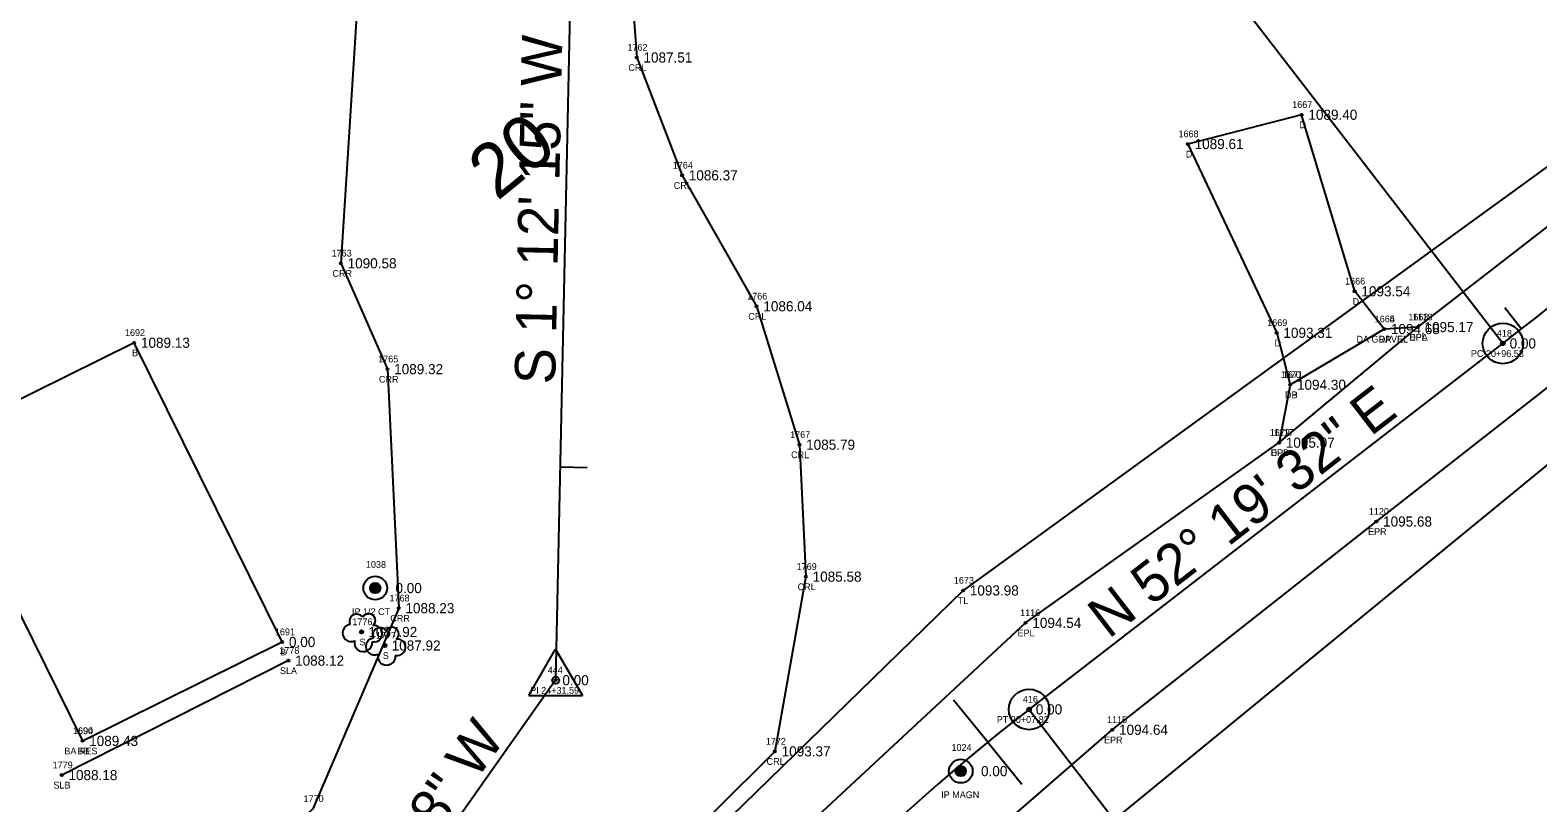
# Model space of a CAD drawing. Extents: x 1539151 to 1541799, y 1198646 to 1201165.
# Drawn here: x 1540139.3 to 1540362.7, y 1199640 to 1199754.4 of the extents above; entities that cross this region are included whole.
import ezdxf

# ---------------------------------------------------------------- set-up
doc = ezdxf.new("R2010")
doc.units = 0
for name, color, linetype in [('RD_EX_Bldg', 7, 'Continuous'), ('RD_EX_Bldg_txCode', 7, 'Continuous'), ('RD_EX_Driveway', 7, 'Continuous'), ('RD_EX_Driveway_txCode', 7, 'Continuous'), ('RD_EX_DV_Prop_txCode', 7, 'Continuous'), ('RD_EX_DV_PropPin', 7, 'Continuous'), ('RD_EX_H2O', 7, 'Continuous'), ('RD_EX_H2O_txCode', 7, 'Continuous'), ('RD_EX_Road', 7, 'Continuous'), ('RD_EX_Road_txCode', 7, 'Continuous'), ('RD_EX_TX_Bldg_ELEV', 7, 'Continuous'), ('RD_EX_TX_Driveway_ELEV', 7, 'Continuous'), ('RD_EX_TX_DV_Prop_ELEV', 7, 'Continuous'), ('RD_EX_TX_H2O_ELEV', 7, 'Continuous'), ('RD_EX_TX_Road_ELEV', 7, 'Continuous'), ('RD_EX_TX_VEG_ELEV', 7, 'Continuous'), ('RD_EX_VEG', 7, 'Continuous'), ('RD_EX_VEG_txCode', 7, 'Continuous'), ('RD_HC_Cl', 7, 'Continuous'), ('RD_HC_Data', 7, 'Continuous'), ('RD_HC_Data_Tic', 7, 'Continuous'), ('RD_HC_Survey_ELEV', 7, 'Continuous'), ('RD_HC_TX_Sta50', 7, 'Continuous'), ('RD_HC_txCode', 7, 'Continuous'), ('RD_SMD_Locator', 7, 'Continuous')]:
    doc.layers.add(name, color=color, linetype=linetype)

msp = doc.modelspace()

# ---------------------------------------------------------------- linework, layer by layer
at = {"layer": 'RD_EX_Bldg'}
msp.add_lwpolyline([(1540147.03, 1199649.13), (1540176.64, 1199663.78), (1540154.7, 1199708.11), (1540125.09, 1199693.46), (1540147.03, 1199649.13)], dxfattribs=at)
at = {"layer": 'RD_EX_Driveway'}
for points in [[(1540339.94, 1199710.14), (1540335.57, 1199715.73), (1540327.71, 1199741.89), (1540310.85, 1199737.55), (1540324.01, 1199709.58), (1540326.02, 1199701.89)], [(1540344.92, 1199710.43), (1540339.94, 1199710.14), (1540326.02, 1199701.89), (1540324.36, 1199693.31)]]:
    msp.add_lwpolyline(points, dxfattribs=at)
at = {"layer": 'RD_EX_DV_PropPin'}
for p, q in [((1540189.86, 1199671.26), (1540189.86, 1199672.29)), ((1540189.9, 1199671.22), (1540189.9, 1199672.32)), ((1540189.93, 1199671.19), (1540189.93, 1199672.35)), ((1540189.97, 1199671.16), (1540189.97, 1199672.38)), ((1540190, 1199671.14), (1540190, 1199672.41)), ((1540190.04, 1199671.12), (1540190.04, 1199672.43)), ((1540190.07, 1199671.1), (1540190.07, 1199672.45)), ((1540190.11, 1199671.08), (1540190.11, 1199672.46)), ((1540190.14, 1199671.06), (1540190.14, 1199672.48)), ((1540190.18, 1199671.05), (1540190.18, 1199672.49)), ((1540190.21, 1199671.04), (1540190.21, 1199672.5)), ((1540190.25, 1199671.03), (1540190.25, 1199672.51)), ((1540190.28, 1199671.02), (1540190.28, 1199672.52)), ((1540190.32, 1199671.02), (1540190.32, 1199672.53)), ((1540190.35, 1199671.01), (1540190.35, 1199672.53)), ((1540190.39, 1199671.01), (1540190.39, 1199672.53)), ((1540190.42, 1199671.01), (1540190.42, 1199672.53)), ((1540190.46, 1199671.01), (1540190.46, 1199672.53)), ((1540190.49, 1199671.01), (1540190.49, 1199672.53)), ((1540190.53, 1199671.02), (1540190.53, 1199672.53)), ((1540190.56, 1199671.02), (1540190.56, 1199672.52)), ((1540190.6, 1199671.03), (1540190.6, 1199672.51)), ((1540190.63, 1199671.04), (1540190.63, 1199672.5)), ((1540190.67, 1199671.05), (1540190.67, 1199672.49)), ((1540190.7, 1199671.06), (1540190.7, 1199672.48)), ((1540190.74, 1199671.08), (1540190.74, 1199672.46)), ((1540190.77, 1199671.1), (1540190.77, 1199672.45)), ((1540190.81, 1199671.12), (1540190.81, 1199672.43)), ((1540190.84, 1199671.14), (1540190.84, 1199672.41)), ((1540190.88, 1199671.16), (1540190.88, 1199672.38)), ((1540190.91, 1199671.19), (1540190.91, 1199672.35)), ((1540190.95, 1199671.22), (1540190.95, 1199672.32)), ((1540190.98, 1199671.26), (1540190.98, 1199672.29)), ((1540189.69, 1199671.58), (1540189.69, 1199671.97)), ((1540189.72, 1199671.47), (1540189.72, 1199672.07)), ((1540189.76, 1199671.4), (1540189.76, 1199672.14)), ((1540189.79, 1199671.35), (1540189.79, 1199672.2)), ((1540189.83, 1199671.3), (1540189.83, 1199672.25)), ((1540191.02, 1199671.3), (1540191.02, 1199672.25)), ((1540191.05, 1199671.35), (1540191.05, 1199672.2)), ((1540191.09, 1199671.4), (1540191.09, 1199672.14)), ((1540191.12, 1199671.47), (1540191.12, 1199672.07)), ((1540191.16, 1199671.58), (1540191.16, 1199671.97)), ((1540276.47, 1199644.45), (1540276.47, 1199644.84)), ((1540276.5, 1199644.35), (1540276.5, 1199644.94)), ((1540276.54, 1199644.28), (1540276.54, 1199645.02)), ((1540276.57, 1199644.22), (1540276.57, 1199645.07)), ((1540276.61, 1199644.17), (1540276.61, 1199645.12)), ((1540276.64, 1199644.13), (1540276.64, 1199645.16)), ((1540276.68, 1199644.1), (1540276.68, 1199645.2)), ((1540276.71, 1199644.06), (1540276.71, 1199645.23)), ((1540276.75, 1199644.04), (1540276.75, 1199645.26)), ((1540276.78, 1199644.01), (1540276.78, 1199645.28)), ((1540276.82, 1199643.99), (1540276.82, 1199645.3)), ((1540276.85, 1199643.97), (1540276.85, 1199645.32)), ((1540276.89, 1199643.95), (1540276.89, 1199645.34)), ((1540276.92, 1199643.94), (1540276.92, 1199645.35)), ((1540276.96, 1199643.93), (1540276.96, 1199645.37)), ((1540276.99, 1199643.92), (1540276.99, 1199645.38)), ((1540277.03, 1199643.91), (1540277.03, 1199645.39)), ((1540277.06, 1199643.9), (1540277.06, 1199645.39)), ((1540277.1, 1199643.89), (1540277.1, 1199645.4)), ((1540277.13, 1199643.89), (1540277.13, 1199645.4)), ((1540277.17, 1199643.89), (1540277.17, 1199645.41)), ((1540277.2, 1199643.89), (1540277.2, 1199645.41)), ((1540277.24, 1199643.89), (1540277.24, 1199645.41)), ((1540277.27, 1199643.89), (1540277.27, 1199645.4)), ((1540277.31, 1199643.89), (1540277.31, 1199645.4)), ((1540277.34, 1199643.9), (1540277.34, 1199645.39)), ((1540277.38, 1199643.91), (1540277.38, 1199645.39)), ((1540277.41, 1199643.92), (1540277.41, 1199645.38)), ((1540277.45, 1199643.93), (1540277.45, 1199645.37)), ((1540277.48, 1199643.94), (1540277.48, 1199645.35)), ((1540277.52, 1199643.95), (1540277.52, 1199645.34)), ((1540277.55, 1199643.97), (1540277.55, 1199645.32)), ((1540277.59, 1199643.99), (1540277.59, 1199645.3)), ((1540277.62, 1199644.01), (1540277.62, 1199645.28)), ((1540277.66, 1199644.04), (1540277.66, 1199645.26)), ((1540277.69, 1199644.06), (1540277.69, 1199645.23)), ((1540277.73, 1199644.1), (1540277.73, 1199645.2)), ((1540277.76, 1199644.13), (1540277.76, 1199645.16)), ((1540277.8, 1199644.17), (1540277.8, 1199645.12)), ((1540277.83, 1199644.22), (1540277.83, 1199645.07)), ((1540277.87, 1199644.28), (1540277.87, 1199645.02)), ((1540277.9, 1199644.35), (1540277.9, 1199644.94)), ((1540277.94, 1199644.45), (1540277.94, 1199644.84))]:
    msp.add_line(p, q, dxfattribs=at)
for centre, radius in [((1540190.42, 1199671.77), 1.75), ((1540190.42, 1199671.77), 0.761), ((1540277.2, 1199644.65), 1.75), ((1540277.2, 1199644.65), 0.761)]:
    msp.add_circle(centre, radius, dxfattribs=at)
at = {"layer": 'RD_EX_H2O'}
for points in [[(1540731.42, 1200240.96), (1540712.61, 1200188.05), (1540690.39, 1200137.17), (1540654.89, 1200108.18), (1540604.41, 1200084.34), (1540543.54, 1200035.6), (1540493.52, 1200006.6), (1540450.33, 1199977.65), (1540405.98, 1199942.24), (1540381.65, 1199909.97), (1540318.96, 1199864.02), (1540266.74, 1199845.63), (1540245.15, 1199841.34), (1540225.71, 1199832.2), (1540201, 1199803.23), (1540187.74, 1199758.03), (1540185.33, 1199719.88), (1540192.23, 1199704.2), (1540193.9, 1199668.79), (1540181.18, 1199639.07), (1540158, 1199617.15)], [(1540745.24, 1200145.69), (1540714.12, 1200111.24), (1540686.99, 1200083.09), (1540635.75, 1200037.11), (1540573.3, 1199996.4), (1540513.92, 1199967.81), (1540469.14, 1199939.84), (1540434.54, 1199909.73), (1540407.32, 1199874.45), (1540364.13, 1199846.32), (1540277.43, 1199809.38), (1540253.91, 1199804.21), (1540226.93, 1199780.46), (1540229.17, 1199750.37), (1540235.89, 1199732.91), (1540246.94, 1199713.51), (1540253.28, 1199693.01), (1540254.24, 1199673.46), (1540249.65, 1199647.58), (1540231.41, 1199629.45), (1540215.51, 1199604.28), (1540200.09, 1199580.59)]]:
    msp.add_lwpolyline(points, dxfattribs=at)
at = {"layer": 'RD_EX_Road'}
for points in [[(1540156.86, 1199508.27), (1540186.51, 1199551.73), (1540214.32, 1199591.31), (1540249.72, 1199632.22), (1540286.8, 1199666.61), (1540324.36, 1199693.31), (1540344.92, 1199710.43), (1540367.33, 1199727.77), (1540402.7, 1199760.37), (1540437.37, 1199795.58), (1540455.74, 1199815.52), (1540466.15, 1199827.23), (1540503.86, 1199868.5), (1540538.69, 1199906.78), (1540571.44, 1199944.18), (1540603.42, 1199982.61), (1540638.15, 1200019.15), (1540672.1, 1200056.68), (1540705.32, 1200094.04), (1540739.01, 1200131.56)], [(1540170.57, 1199494.63), (1540181.23, 1199508.28), (1540202.24, 1199541.54), (1540230.14, 1199581.95), (1540262.76, 1199618.79), (1540299.65, 1199650.78), (1540338.78, 1199681.63), (1540378.45, 1199712.68), (1540416.67, 1199747.15), (1540451.68, 1199783.64), (1540485.11, 1199820.19), (1540518.57, 1199856.95), (1540552.63, 1199894.89), (1540585.47, 1199932.32), (1540619.12, 1199969.78), (1540652.74, 1200007.33), (1540685.87, 1200044.5), (1540718.68, 1200081.33), (1540762.24, 1200130.19)]]:
    msp.add_lwpolyline(points, dxfattribs=at)
at = {"layer": 'RD_EX_VEG'}
msp.add_line((1540177.55, 1199661.02), (1540143.96, 1199644.07), dxfattribs=at)
for points in [[(1540712.01, 1200109.09), (1540564.8, 1199952.12), (1540511.25, 1199924.62), (1540488.55, 1199863.43), (1540394.02, 1199755.91), (1540277.54, 1199671.42), (1540233.54, 1199628.53), (1540200.18, 1199585.62), (1540155.93, 1199516.08), (1540069.9, 1199571.55)], [(1540836.37, 1200082.45), (1540794.45, 1200101.71), (1540758.65, 1200106.39), (1540697.29, 1200033.83), (1540560.39, 1199886.45), (1540422.51, 1199739.87), (1540382.08, 1199704.72), (1540267.52, 1199610.92), (1540233.68, 1199579.65), (1540209.33, 1199537.96), (1540187.75, 1199496.51), (1540221.64, 1199381.22)]]:
    msp.add_lwpolyline(points, dxfattribs=at)
for centre in [(1540188.4, 1199665.27), (1540191.86, 1199663.26)]:
    msp.add_circle(centre, 0.25, dxfattribs=at)
for centre, radius, start, end in [((1540187.68, 1199666.82), 1.08, 34.9763, 204.756), ((1540189.45, 1199666.98), 0.995, 308.7626, 152.0467), ((1540186.84, 1199665.12), 1.26, 96.4518, 294.734), ((1540190.24, 1199665), 1.22, 256.5667, 98.1046), ((1540191.14, 1199664.81), 1.08, 34.9763, 204.756), ((1540192.91, 1199664.97), 0.995, 308.7626, 152.0467), ((1540188.65, 1199663.68), 1.32, 166.8827, 5.7589), ((1540190.3, 1199663.11), 1.26, 96.4518, 294.734), ((1540193.7, 1199662.98), 1.22, 256.5667, 98.1046), ((1540192.11, 1199661.67), 1.32, 166.8827, 5.7589)]:
    msp.add_arc(centre, radius, start, end, dxfattribs=at)
at = {"layer": 'RD_HC_Cl'}
for p, q in [((1540219.98, 1199792.28), (1540217.16, 1199658.12)), ((1540287.32, 1199653.79), (1540357.53, 1199708.01)), ((1540217.16, 1199658.12), (1540172.44, 1199594.87))]:
    msp.add_line(p, q, dxfattribs=at)
for centre, radius, start, end in [((1539929.71, 1200262.06), 700, 307.67455, 318.32753), ((1540470.67, 1199416.35), 300, 127.6745, 145.5923)]:
    msp.add_arc(centre, radius, start, end, dxfattribs=at)
at = {"layer": 'RD_HC_Data'}
for p, q in [((1540357.53, 1199708.01), (1540286.37, 1199800.18)), ((1540213.19, 1199655.83), (1540217.16, 1199662.71)), ((1540217.16, 1199662.71), (1540221.13, 1199655.83)), ((1540213.19, 1199655.83), (1540221.13, 1199655.83)), ((1540287.32, 1199653.79), (1540357.97, 1199562.31))]:
    msp.add_line(p, q, dxfattribs=at)
for centre, radius in [((1540357.53, 1199708.01), 3), ((1540357.53, 1199708.01), 0.282), ((1540217.16, 1199658.12), 0.529), ((1540287.32, 1199653.79), 3), ((1540287.32, 1199653.79), 0.282)]:
    msp.add_circle(centre, radius, dxfattribs=at)
at = {"layer": 'RD_HC_Data_Tic'}
for p, q in [((1540360.28, 1199710.14), (1540357.82, 1199713.29)), ((1540217.83, 1199689.71), (1540221.83, 1199689.62)), ((1540281.2, 1199648.94), (1540276.14, 1199655.14)), ((1540281.2, 1199648.94), (1540286.25, 1199642.73))]:
    msp.add_line(p, q, dxfattribs=at)
at = {"layer": 'RD_SMD_Locator'}
for centre in [(1540229.17, 1199750.37), (1540327.71, 1199741.89), (1540310.85, 1199737.55), (1540235.89, 1199732.91), (1540185.33, 1199719.88), (1540335.57, 1199715.73), (1540246.94, 1199713.51), (1540339.94, 1199710.14), (1540339.94, 1199710.14), (1540344.92, 1199710.43), (1540344.92, 1199710.43), (1540154.7, 1199708.11), (1540324.01, 1199709.58), (1540357.53, 1199708.01), (1540192.23, 1199704.2), (1540326.02, 1199701.89), (1540326.02, 1199701.89), (1540253.28, 1199693.01), (1540324.36, 1199693.31), (1540324.36, 1199693.31), (1540338.78, 1199681.63), (1540254.24, 1199673.46), (1540190.42, 1199671.77), (1540277.54, 1199671.42), (1540193.9, 1199668.79), (1540286.8, 1199666.61), (1540176.64, 1199663.78), (1540188.4, 1199665.27), (1540191.86, 1199663.26), (1540177.55, 1199661.02), (1540217.16, 1199658.12), (1540287.32, 1199653.79), (1540299.65, 1199650.78), (1540147.03, 1199649.13), (1540147.03, 1199649.13), (1540249.65, 1199647.58), (1540143.96, 1199644.07), (1540277.2, 1199644.65)]:
    msp.add_circle(centre, 0.15, dxfattribs=at)

# ---------------------------------------------------------------- texts
at = {"layer": 'RD_EX_Bldg_txCode'}
for s, p in [('1692', (1540153.33, 1199709.11)), ('B', (1540154.39, 1199706.11)), ('1691', (1540175.55, 1199664.78)), ('B', (1540176.33, 1199661.78)), ('1690', (1540145.62, 1199650.13)), ('1694', (1540145.66, 1199650.13)), ('BA RES', (1540144.35, 1199647.13)), ('BB', (1540146.25, 1199647.13))]:
    msp.add_text(s, height=1, dxfattribs=at).set_placement(p)
at = {"layer": 'RD_EX_Driveway_txCode'}
for s, p in [('1667', (1540326.31, 1199742.89)), ('1668', (1540309.46, 1199738.55)), ('D', (1540327.4, 1199739.89)), ('D', (1540310.54, 1199735.55)), ('1666', (1540334.15, 1199716.73)), ('D', (1540335.26, 1199713.73)), ('1669', (1540322.61, 1199710.58)), ('1664', (1540338.54, 1199711.14)), ('1665', (1540338.54, 1199711.14)), ('1663', (1540343.52, 1199711.43)), ('D', (1540323.7, 1199707.58)), ('DA GRAVEL', (1540335.83, 1199708.14)), ('DP', (1540339.16, 1199708.14)), ('DPA', (1540343.65, 1199708.43)), ('1670', (1540324.61, 1199702.89)), ('1671', (1540324.93, 1199702.89)), ('DB', (1540325.24, 1199699.89)), ('DP', (1540325.24, 1199699.89)), ('1672', (1540322.99, 1199694.31)), ('DPB', (1540323.11, 1199691.31))]:
    msp.add_text(s, height=1, dxfattribs=at).set_placement(p)
at = {"layer": 'RD_EX_DV_Prop_txCode'}
for s, p in [('1038', (1540189.04, 1199674.77)), ('IP 1/2 CT', (1540186.97, 1199667.77)), ('1024', (1540275.82, 1199647.65)), ('IP MAGN', (1540274.29, 1199640.65))]:
    msp.add_text(s, height=1, dxfattribs=at).set_placement(p)
at = {"layer": 'RD_EX_H2O_txCode'}
for s, p in [('1762', (1540227.8, 1199751.37)), ('CRL', (1540227.94, 1199748.37)), ('1764', (1540234.52, 1199733.91)), ('CRL', (1540234.66, 1199730.91)), ('1763', (1540183.96, 1199720.88)), ('CRR', (1540184.08, 1199717.88)), ('1766', (1540245.54, 1199714.51)), ('CRL', (1540245.71, 1199711.51)), ('1765', (1540190.86, 1199705.2)), ('CRR', (1540190.97, 1199702.2)), ('1767', (1540251.91, 1199694.01)), ('CRL', (1540252.05, 1199691.01)), ('1769', (1540252.87, 1199674.46)), ('CRL', (1540253.02, 1199671.46)), ('1768', (1540192.53, 1199669.79)), ('CRR', (1540192.65, 1199666.79)), ('1772', (1540248.31, 1199648.58)), ('CRL', (1540248.42, 1199645.58)), ('1770', (1540179.8, 1199640.07))]:
    msp.add_text(s, height=1, dxfattribs=at).set_placement(p)
at = {"layer": 'RD_EX_Road_txCode'}
for s, p in [('1118', (1540344.14, 1199711.43)), ('EPL', (1540343.71, 1199708.43)), ('1117', (1540323.58, 1199694.31)), ('EPL', (1540323.16, 1199691.31)), ('1120', (1540337.67, 1199682.63)), ('EPR', (1540337.55, 1199679.63)), ('1116', (1540286, 1199667.61)), ('EPL', (1540285.6, 1199664.61)), ('1115', (1540298.87, 1199651.78)), ('EPR', (1540298.42, 1199648.78))]:
    msp.add_text(s, height=1, dxfattribs=at).set_placement(p)
at = {"layer": 'RD_EX_TX_Bldg_ELEV'}
for s, p in [('1089.13', (1540155.7, 1199707.36)), ('0.00', (1540177.64, 1199663.03)), ('1089.43', (1540148.03, 1199648.38)), ('1089.43', (1540148.03, 1199648.38))]:
    msp.add_text(s, height=1.5, dxfattribs=at).set_placement(p)
at = {"layer": 'RD_EX_TX_Driveway_ELEV'}
for s, p in [('1089.40', (1540328.71, 1199741.14)), ('1089.61', (1540311.85, 1199736.8)), ('1093.54', (1540336.57, 1199714.98)), ('1093.31', (1540325.01, 1199708.83)), ('1094.68', (1540340.94, 1199709.39)), ('1094.68', (1540340.94, 1199709.39)), ('1095.17', (1540345.92, 1199709.68)), ('1094.30', (1540327.02, 1199701.14)), ('1094.30', (1540327.02, 1199701.14)), ('1095.07', (1540325.36, 1199692.56))]:
    msp.add_text(s, height=1.5, dxfattribs=at).set_placement(p)
at = {"layer": 'RD_EX_TX_DV_Prop_ELEV'}
for p in [(1540193.42, 1199671.02), (1540280.2, 1199643.9)]:
    msp.add_text('0.00', height=1.5, dxfattribs=at).set_placement(p)
at = {"layer": 'RD_EX_TX_H2O_ELEV'}
for s, p in [('1087.51', (1540230.17, 1199749.62)), ('1086.37', (1540236.89, 1199732.16)), ('1090.58', (1540186.33, 1199719.13)), ('1086.04', (1540247.94, 1199712.76)), ('1089.32', (1540193.23, 1199703.45)), ('1085.79', (1540254.28, 1199692.26)), ('1085.58', (1540255.24, 1199672.71)), ('1088.23', (1540194.9, 1199668.04)), ('1093.37', (1540250.65, 1199646.83))]:
    msp.add_text(s, height=1.5, dxfattribs=at).set_placement(p)
at = {"layer": 'RD_EX_TX_Road_ELEV'}
for s, p in [('1095.17', (1540345.92, 1199709.68)), ('1095.07', (1540325.36, 1199692.56)), ('1095.68', (1540339.78, 1199680.88)), ('1094.54', (1540287.8, 1199665.86)), ('1094.64', (1540300.65, 1199650.03))]:
    msp.add_text(s, height=1.5, dxfattribs=at).set_placement(p)
at = {"layer": 'RD_EX_TX_VEG_ELEV'}
for s, p in [('1093.98', (1540278.54, 1199670.67)), ('1087.92', (1540189.4, 1199664.52)), ('1087.92', (1540192.86, 1199662.51)), ('1088.12', (1540178.55, 1199660.27)), ('1088.18', (1540144.96, 1199643.32))]:
    msp.add_text(s, height=1.5, dxfattribs=at).set_placement(p)
at = {"layer": 'RD_EX_VEG_txCode'}
for s, p in [('1673', (1540276.17, 1199672.42)), ('TL', (1540276.77, 1199669.42)), ('1776', (1540187.03, 1199666.27)), ('S', (1540188.1, 1199663.27)), ('1777', (1540190.52, 1199664.26)), ('1778', (1540176.2, 1199662.02)), ('S', (1540191.55, 1199661.26)), ('SLA', (1540176.3, 1199659.02)), ('1779', (1540142.61, 1199645.07)), ('SLB', (1540142.73, 1199642.07))]:
    msp.add_text(s, height=1, dxfattribs=at).set_placement(p)
at = {"layer": 'RD_HC_Data'}
for s, rotation, p in [('S 1%%d 12\' 15" W', 88.7958, (1540217.08, 1199701.91)), ('N 52%%d 19\' 32" E', 37.6745, (1540299.1, 1199664.15)), ('S 35%%d 15\' 38" W', 54.7394, (1540177.34, 1199603.52))]:
    msp.add_text(s, height=6, rotation=rotation, dxfattribs=at).set_placement(p)
at = {"layer": 'RD_HC_Survey_ELEV'}
for p in [(1540358.53, 1199707.26), (1540218.16, 1199657.37), (1540288.32, 1199653.05)]:
    msp.add_text('0.00', height=1.5, dxfattribs=at).set_placement(p)
at = {"layer": 'RD_HC_TX_Sta50'}
msp.add_text('20', height=8, rotation=39.1678, dxfattribs=at).set_placement((1540208.49, 1199729.01))
at = {"layer": 'RD_HC_txCode'}
for s, p in [('418', (1540356.64, 1199709.01)), ('PC 20+96.53', (1540352.79, 1199706.01)), ('444', (1540215.98, 1199659.12)), ('PI 24+31.59', (1540213.38, 1199656.12)), ('416', (1540286.4, 1199654.8)), ('PT 20+07.82', (1540282.53, 1199651.8))]:
    msp.add_text(s, height=1, dxfattribs=at).set_placement(p)

doc.saveas('drawing.dxf')
